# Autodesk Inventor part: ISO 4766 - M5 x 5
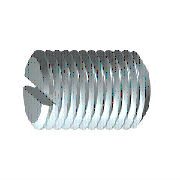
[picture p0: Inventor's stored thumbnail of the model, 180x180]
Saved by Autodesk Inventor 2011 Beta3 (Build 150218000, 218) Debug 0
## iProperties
IsCustomPart: 0
Created: 2008-01
Part Number: ISO 4766 - M5 x 5
Material: Stainless Steel, 440C
Description: Slotted Headless Set Screw - Flat Point
Document SubType Name: Modeling
Standard: ISO 4766
Designer: latalom
Standard Revision: First edition 1983-09-01
Standards Organization: ISO
Language: en-US
Size Designation: M5 x 5
Categories: <MemberInstance><Categories><Category DisplayName="Fasteners" InternalName="e4da775c-781d-43d5-af7c-5136215cf5a6" Mnemonic="FSTN"><Category DisplayName="Bolts"
Density: 7.75 g/cm^3
Mass: 0.682426 g
Surface Area: 1.16465 cm^2
Volume: 0.088055 cm^3
Author: latalom
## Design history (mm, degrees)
revolve "Body" stored, may be unused: angle "d6" = 90 deg
sketch "Sketch2"
  geometry: L1 (5, 2.009)-(5, -2.009) reference; L2 (3.464, 0)-(5.256, 0) reference; L3 (5, 0.4)-(3.72, 0.4); L4 (3.72, 0.4)-(3.72, 0); L5 (3.72, -0.4)-(3.72, 0); L6 (3.72, -0.4)-(5, -0.4)
  constraints: 8 end point, 3 point on line, 2 perpendicular, 1 parallel, 1 symmetric about line, 1 other
  dimensions: "d8" = 0.4 distance between parallel lines of L2 L3 (= 0.5 x SBR); "d9" = 1.28 distance between parallel lines of L1 L4 (= STI)
extrude "Slot1" cut sketch "Sketch2" stored distance "d10" = 5 (= NND); taper "d11" = 0 deg
workaxis "Work Axis1"
workplane "Work Plane1"
body "Solid1"
chamfer "Chamfer1" distance "d3" = 0.49076 (= -0.5 x GD1 + 0.5 x NND); stored, may be unused: angle "d4" = 60 deg (= FAWI), second distance "d34" = 0.49076 (= -0.5 x GD1 + 0.5 x NND)
feature "Thread" dims "d5" = 5 (= NLG), "d7" = 0
chamfer "Chamfer2" distance "d13" = 0.43301 (computed from NND, SPD, FAWI); stored, may be unused: angle "d14" = 60 deg (= FAWI), second distance "d35" = 0.43301 (computed from NND, SPD, FAWI)
sketch "Sketch1"
  geometry: L1 (0, 0)-(5, 0); L2 (5, 0)-(5, 2.5); L3 (5, 2.5)-(0, 2.5); L4 (0, -0.5)-(0, 3) reference; L5 (0, 2.5)-(0, 0)
  constraints: 9 end point, 2 parallel, 2 perpendicular, 1 collinear, 1 point on line
  dimensions: "d0" = 5 diameter of L3 L1 (= NND); "d2" = 5 distance from line of L2 L3.end (= NLG)
other parameters: "NND" = 5 [user parameter; used in 6 equation terms], "NLG" = 5 [user parameter; used in 2 equation terms], "FAWI" = 60 deg [user parameter; used in 4 equation terms], "GD1" = 4.01848 (= THREADDIA - 1.2269 x PTC) [user parameter; used in 2 equation terms], "d1" = 0, "FAWI1" = 45 deg [user parameter], "SPD" = 3.5 [user parameter; used in 2 equation terms], "SBR" = 0.8 [user parameter; used in 1 equation term], "STI" = 1.28 [user parameter; used in 1 equation term], "d15" = 0, "d36" = 90 deg, "d37" = 0, "GUL" = 0.49076 (= 0.61345 x PTC) [user parameter], "TPU" = 12.5 (computed from PTC) [user parameter], "THREADDIA" = 5 [user parameter; used in 1 equation term], "TOA" = 30 deg [user parameter], "PTC" = 0.8 [user parameter; used in 4 equation terms], "GAL" = 0.49076 (= 0.61345 x PTC) [user parameter]
